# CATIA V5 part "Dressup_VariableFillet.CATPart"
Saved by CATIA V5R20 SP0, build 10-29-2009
Part number: Part7
Bounding box of the stored display mesh (mm): x -75 to 79, y -51.528 to 47.265, z -28.473 to 59.079
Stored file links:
  G:\카티아자료\수업자료\툴바예제\2 PartDesign\Dressup_VariableFillet.CATPart
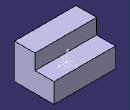
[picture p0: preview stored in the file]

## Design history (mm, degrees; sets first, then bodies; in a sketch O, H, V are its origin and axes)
AxisSystem1: origin (0, 0, 0), X (1, 0, 0), Y (0, 1, 0), Z (0, 0, 1)
Body1 (main body)
  Sketch1 on YZ plane of AxisSystem1, origin (0, 0, 0), H (0, 1, 0), V (0, 0, 1)
    line L1 (47.265, -28.4733) -> (-51.5276, -28.4733)
    line L2 (-51.5276, -28.4733) -> (-51.5276, 59.0789)
    line L3 (-51.5276, 59.0789) -> (0, 59.0789)
    point P4 (0, 59.0789)
    line L4 (0, 59.0789) -> (0, 20.9473)
    line L5 (0, 20.9473) -> (47.265, 20.9473)
    line L6 (47.265, 20.9473) -> (47.265, -28.4733)
    horizontal: L1 H, L3 H, L5 H
    vertical: L2 V, L4 V, L6 V
    coincidence: P4 V
  Pad1: profile Sketch1, direction (1, 0, 0), length 79, opposite side length 75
